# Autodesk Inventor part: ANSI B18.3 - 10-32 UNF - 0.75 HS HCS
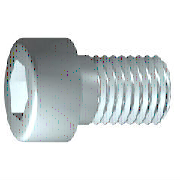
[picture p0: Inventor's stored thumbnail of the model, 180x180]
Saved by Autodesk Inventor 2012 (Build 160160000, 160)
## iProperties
IsCustomPart: 0
Created: 2011-02
Part Number: ANSI B18.3 - 10-32 UNF - 0.75 HS HCS
Material: Steel, Mild
Description: Hexagon Socket Head Cap Screw
Document SubType Name: Modeling
Standard: ANSI B18.3
Designer: Owner
Standard Revision: 2003
Standards Organization: ANSI
Language: en-US
Size Designation: 10-32 UNF - 0.75
Categories: <MemberInstance><Categories><Category DisplayName="Fasteners" InternalName="e4da775c-781d-43d5-af7c-5136215cf5a6" Mnemonic="FSTN"><Category DisplayName="Bolts"
Density: 7.86 g/cm^3
Mass: 4.28992 g
Surface Area: 5.32255 cm^2
Volume: 0.545791 cm^3
Author: Owner
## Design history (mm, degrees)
body "Solid1"
workplane "Work Plane1"
fillet "Fillet2" dims "d30" = 0.1524 (= R)
revolve "Body" stored, may be unused: angle "d10" = 90 deg
sketch "Sketch2"
  geometry: L1 (0, -5.547)-(0, 5.547) reference; L2 (-5.547, 0)-(5.547, 0) reference; L3 (2.288, 0)-(1.144, -1.981); L4 (1.144, -1.981)-(-1.144, -1.981); L5 (-1.144, -1.981)-(-2.288, 0); L6 (-2.288, 0)-(-1.144, 1.981); L7 (-1.144, 1.981)-(1.144, 1.981); L8 (1.144, 1.981)-(2.288, 0); 2 further points
  constraints: 12 end point, 1 coincident, 1 horizontal alignment, 1 point on line, 12 other
extrude "Slot" join sketch "Sketch2" stored distance "d11" = 10; taper "d12" = 0 deg
fillet "Fillet1" dims "d17" = 0.4572 (= RR)
feature "Thread" dims "d13" = 17.85905 (= GEL), "d14" = 0
chamfer "Chamfer1" distance "d15" = 0.47244 (= -0.5 x SPD + 0.5 x GD); stored, may be unused: second distance "d16" = 0.47244 (= GUL), angle "d27" = 45 deg
sketch "Sketch1"
  geometry: L1 (-1.219, 0)-(19.05, 0); L2 (19.05, 0)-(19.05, 2.413); L3 (19.05, 2.413)-(1.191, 2.413); L4 (1.191, 2.413)-(0, 2.413); L5 (0, 2.413)-(0, 2.413); L6 (0, 2.413)-(0, 3.962); L7 (0, 3.962)-(-4.826, 3.962); L8 (-4.826, 3.962)-(-4.826, 2.288); L9 (-4.826, 2.288)-(-2.54, 2.288); L10 (-2.54, 2.288)-(-1.219, 0); L11 (-9.601, 0)-(23.825, 0) reference; L12 (0, -0.792)-(0, 4.755) reference; L13 (1.191, 2.413)-(0, 2.413)
  constraints: 22 end point, 6 parallel, 2 collinear, 2 perpendicular, 1 horizontal, 1 point on line
  dimensions: "d1" = 17.85905 distance from line of L3.end L2 (= GEL); "d2" = 1.19085 distance of L4.end L3.end (computed from GAL); "d3" = 4.826 distance between parallel lines of L8 L6 (= KOH); "d4" = 2.286 distance of L8.end L9.end (= INTI); "d5" = 60 deg angle of L10 L1; "d6" = 4.826 diameter of L3 L1 (= GD); "d7" = 4.826 diameter of L5 L1 (= BDM); "d8" = 4.57539 diameter of L9 L1 (= 1.1547 x SW); "d9" = 7.9248 diameter of L7 L1 (= KOD); "d26" = 19.05 distance between parallel lines of L12 L2 (= NLG)
other parameters: "GD" = 4.826 [user parameter; used in 2 equation terms], "NLG" = 19.05 [user parameter; used in 1 equation term], "GEL" = 17.85905 [user parameter; used in 2 equation terms], "KOD" = 7.9248 [user parameter; used in 1 equation term], "KOH" = 4.826 [user parameter; used in 1 equation term], "INTI" = 2.286 [user parameter; used in 1 equation term], "GAL" = 1.19075 [user parameter; used in 1 equation term], "GUL" = 0.47244 [user parameter; used in 1 equation term], "BDM" = 4.826 [user parameter; used in 1 equation term], "SW" = 3.9624 [user parameter; used in 2 equation terms], "RR" = 0.4572 [user parameter; used in 1 equation term], "SPD" = 3.88112 [user parameter; used in 2 equation terms], "d19" = 0, "d28" = 0, "d29" = 0, "R" = 0.1524 [user parameter; used in 1 equation term], "PHH" = 0.127 [user parameter], "GD1" = 3.88112 (= SPD) [user parameter], "THREADDIA" = 4.826 [user parameter], "FAWI" = 45 deg [user parameter], "PTC" = 0.79375 (computed from TPU) [user parameter], "KOH1" = 4.3434 [user parameter], "NND" = 4.826 [user parameter], "TOA" = 30 deg [user parameter], "E0" = 4.57657 (= 1.155 x SW) [user parameter]
